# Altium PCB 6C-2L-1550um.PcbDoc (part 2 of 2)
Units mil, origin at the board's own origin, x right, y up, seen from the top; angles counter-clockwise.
Board outline 3937.01 x 2952.76 mil, 2 copper layers (Top Layer, Bottom Layer), stack 62.442 mil thick; 172 components, 97 nets, 523 pads, 239 vias.
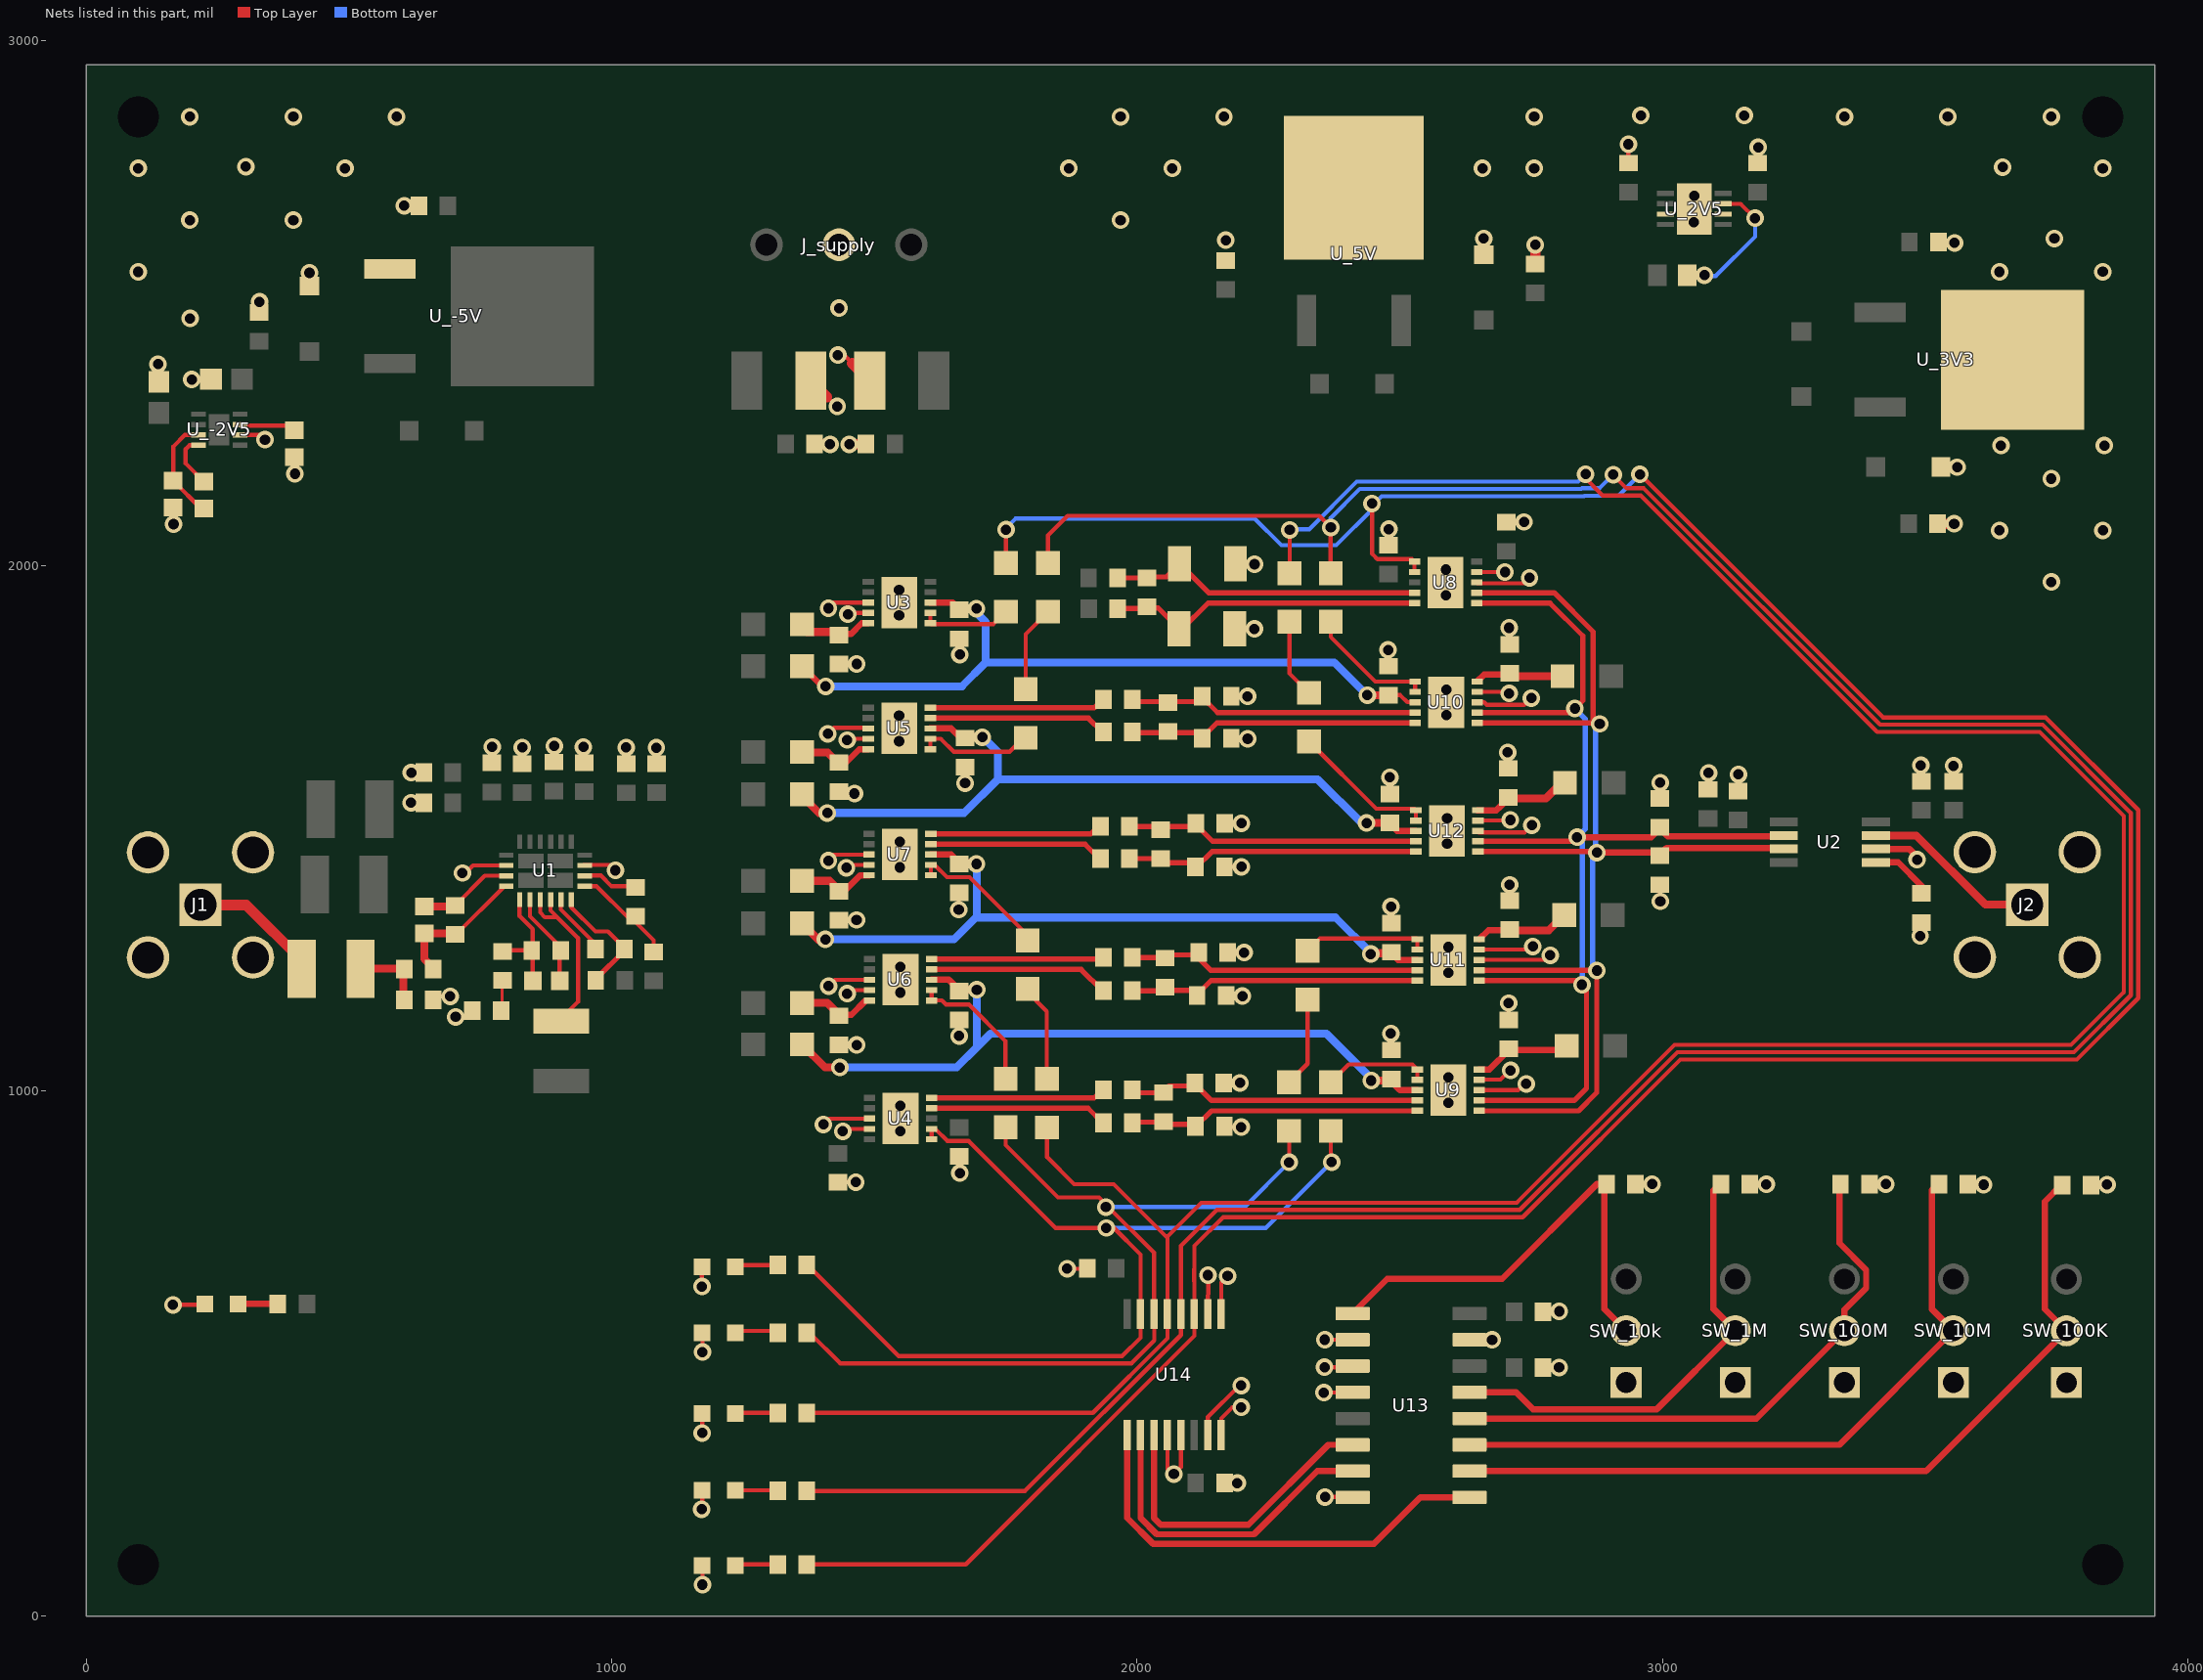
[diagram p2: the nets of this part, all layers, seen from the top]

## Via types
v1: diameter 33.46, hole 19.68, Top Layer to Bottom Layer, 215 vias
v2: diameter 37/37 (per signal layer), hole 19.7, Top Layer to Bottom Layer, 16 vias
v3: diameter 33.47, hole 19.69, Top Layer to Bottom Layer, 4 vias
v4: diameter 37, hole 19.7, Top Layer to Bottom Layer, 4 vias

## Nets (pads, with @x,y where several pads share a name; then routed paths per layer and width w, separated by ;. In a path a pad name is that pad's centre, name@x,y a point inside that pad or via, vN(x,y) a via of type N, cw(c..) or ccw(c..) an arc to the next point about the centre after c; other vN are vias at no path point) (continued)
Diff_pair3_N: R8.2 U4.9 | length 337.2
  Top Layer w9.84: U4.9@1608.96,966.96 1906.56,966.96 R8.2@1933.87,939.65 ; R8.2@1933.87,939.65 1933.87,939.15 R8.2@1933.87,939.65
Diff_pair3_P: R7.2 U4.10 | length 336.6
  Top Layer w9.84: U4.10@1608.96,986.64 1918.15,986.64 1933.86,1002.35 R7.2@1933.86,997.18
Diff_pair4_N: R10.2 U5.9 | length 338.5
  Top Layer w9.84: U5.9@1606.39,1709.48 1907.3,1709.48 R10.2@1933.87,1682.91
Diff_pair4_P: R9.2 U5.10 | length 343.3
  Top Layer w9.84: U5.10@1606.39,1729.17 1917.91,1729.17 1933.86,1745.12 R9.2@1927.33,1751.65
Diff_pair5_N: R11.2 U6.10 | length 326.5
  Top Layer w9.84: U6.10@1608.7,1250.8 1930.82,1250.8 R11.2@1933.9,1253.88
Diff_pair5_P: R12.2 U6.9 | length 342
  Top Layer w9.84: U6.9@1608.7,1231.11 1893.46,1231.11 R12.2@1933.9,1190.67
Diff_pair6_N: R14.2 U7.9 | length 332
  Top Layer w9.84: U7.9@1607.43,1469.45 1900.99,1469.45 R14.2@1928.2,1442.24
Diff_pair6_P: R13.2 U7.10 | length 327.8
  Top Layer w9.84: U7.10@1607.43,1489.14 1911.27,1489.14 1926.79,1504.66 R13.2@1928.21,1503.24
Diff_Pair9_N: Rmatch-.2 U2.3 U8.2 U9.1 U10.1 U11.2 U12.1 | length 2443
  Top Layer w9.84: U8.2@2646.2,1948.23 2794.1,1948.23 2868.14,1874.19 2868.14,1703.11 v1@2870.86,1700.39 ; U10.1@2647.16,1700.39 v1@2870.86,1700.39 ; U12.1@2647.91,1455.48 2872.84,1455.48 2874.88,1453.44 v1(2875.23,1453.44) ; U9.1@2651.45,962.11 2840.28,962.11 2875.06,996.89 2875.06,1227.48 2876.08,1228.49 2879.04,1228.49 2880.19,1229.64 2875.06,1229.64 U11.2@2651.45,1229.64 ; v1(2875.38,1229.08) v1@2875.38,1229.64 ; v1(2880.59,1698.57) 2877.22,1698.57 2874.31,1698.57 2873.89,1698.57 2872.68,1698.57 v1@2870.86,1700.39 ; Rmatch-.2@2991.09,1453.44 Rmatch-.2@2995.1,1449.43
  Top Layer w12: v1@2874.88,1453.44 Rmatch-.2@2991.09,1453.44 ; Rmatch-.2@2995.1,1449.43 3008.21,1462.53 3228.92,1462.53 U2.3@3230.89,1460.56
  Bottom Layer w9.84: v1(2875.23,1453.44) v1@2874.88,1453.44 ; v1(2875.38,1229.08) v1(2875.38,1229.08) 2867.36,1237.21 2867.36,1445.92 v1@2874.88,1453.44 ; v1(2880.59,1698.57) 2877.22,1698.57 2872.6,1698.57 2872.6,1455.72 v1@2874.88,1453.44
Diff_Pair9_P: Rmatch+.2 U2.2 U8.1 U9.2 U10.2 U11.1 U12.2 | length 2308.6
  Top Layer w9.84: U8.1@2646.2,1928.54 2785.95,1928.54 2848.46,1866.03 2848.46,1742.99 v1(2833.41,1727.95) ; U10.2@2647.16,1720.07 v1@2825.61,1720.07 ; U12.2@2647.91,1475.17 2829.81,1475.17 v1(2837.68,1483.04) ; U9.2@2651.45,981.79 2832.13,981.79 2855.38,1005.05 2855.38,1193.43 2838.85,1209.96 U11.1@2651.45,1209.96
  Top Layer w12: v1(2837.68,1483.04) 2847.04,1483.04 2978.53,1483.04 2994.96,1499.47 3010.05,1484.38 3229.11,1484.38 U2.2@3230.89,1486.15
  Bottom Layer w9.84: v1(2833.41,1727.95) 2853.03,1708.33 2853.03,1706.84 2852.91,1706.73 2852.91,1498.28 2844.96,1490.32 v1(2837.68,1483.04) 2847.67,1473.05 2847.67,1203.03 v1(2846.73,1202.08)
Diff_pair21_N: C6.2 C15.1 R6.1 U8.10 | length 600.3
  Top Layer w9.84: R6.1@1964.95,1918.11 2017.58,1918.11 2018.64,1919.17 2039.99,1919.17 C6.2@2079.67,1879.48 2086.12,1879.48 2135.18,1928.54 U8.10@2528.09,1928.54
Diff_pair21_P: C5.2 C15.2 R5.1 U8.9 | length 598.3
  Top Layer w9.84: R5.1@1964.65,1976.3 2016.71,1976.3 2018.64,1978.23 2055.86,1978.23 C5.2@2080.88,2003.25 2135.9,1948.23 2525.83,1948.23 2526.96,1949.35 U8.9@2528.09,1948.23
Diff_pair31_N: C8.2 C16.1 R8.1 U9.10 | length 555
  Top Layer w9.84: R8.1@1986.43,940.54 2037.78,940.54 C16.1@2041.07,937.26 ; C16.1@2050.31,939.67 2053.83,936.15 2105.69,936.15 2109.25,932.59 2112.03,932.59 2141.55,962.11 U9.10@2534.14,962.11
Diff_pair31_P: C7.2 C16.2 R7.1 U9.9 | length 552
  Top Layer w9.84: R7.1@1992.92,1002.35 1998.96,996.32 C16.2@2041.07,996.32 ; C16.2@2050.31,998.73 2060.86,1009.28 C7.2@2108.2,1009.28 ; C7.2@2108.09,1015.32 2141.62,981.79 2141.85,981.79 U9.9@2533.34,981.79
Diff_pair41_N: C10.2 C17.1 R10.1 U10.10 | length 553.9
  Top Layer w9.84: R10.1@1992.03,1681.8 2058.87,1681.8 2111.15,1681.8 2122.22,1670.74 2151.87,1700.39 U10.10@2529.05,1700.39
Diff_pair41_P: C9.2 C17.2 R9.1 U10.9 | length 552.7
  Top Layer w9.84: R9.1@1992.92,1745.12 1997.18,1740.86 2058.87,1740.86 2116.77,1740.86 C9.2@2121.99,1746.07 ; C9.2@2122.22,1751.11 2153.25,1720.08 U10.9@2529.05,1720.08
Diff_pair51_N: C12.2 C18.1 R12.1 U11.10 | length 561.3
  Top Layer w9.84: R12.1@1994.78,1189.53 1996.99,1189.53 1998.12,1190.67 2048.4,1190.67 2053.4,1195.67 2057.72,1191.34 2105.74,1191.34 C12.2@2114.07,1183.01 ; C12.2@2112.27,1181.2 C12.2@2114.07,1183.01 ; U11.10@2534.58,1209.96 2356.45,1209.96 2297.32,1209.96 2141.02,1209.96 C12.2@2114.07,1183.01
Diff_pair51_P: C11.2 C18.2 R11.1 U11.9 | length 573.3
  Top Layer w9.84: R11.1@1992.96,1253.88 2052.55,1253.88 2053.4,1254.72 2057.3,1258.62 2103.39,1258.62 2111.73,1266.96 2115.1,1270.33 2115.1,1263.59 2115.34,1263.36 2115.34,1254.24 2139.94,1229.64 2289.17,1229.64 2364.61,1229.64 U11.9@2533.34,1229.64
Diff_pair61_N: C14.2 C19.1 R14.1 U12.10 | length 558.7
  Top Layer w9.84: R14.1@1987.26,1442.24 C19.1@2043.43,1442.24 ; C19.1@2045.23,1440 2051.2,1434.03 2101.28,1434.03 2109.25,1426.06 2113.05,1426.06 2142.47,1455.48 U12.10@2529.8,1455.48
Diff_pair61_P: C13.2 C19.2 R13.1 U12.9 | length 558.9
  Top Layer w9.84: R13.1@1987.26,1503.24 2045.37,1503.24 2103.82,1503.24 2109.55,1508.98 2143.36,1475.17 U12.9@2529.8,1475.17
GND: C1_supU1.2 C1_supU2.1 C1_U3.1 C1_U4.1 C1_U5.1 C1_U6.1 C1_U7.1 C1_U8.1 C1_U9.1 C1_U10.1 C1_U11.1 C1_U12.1 C2_supU1.2 C2_supU2.1 C2_U3.1 C2_U4.1 C2_U5.1 C2_U6.1 C2_U7.1 C2_U8.1 C2_U9.1 C2_U10.1 C2_U11.1 C2_U12.1 C3_supU1.2 C4_supU1.2 C5.1 C6.1 C7.1 C8.1 C9.1 C10.1 C11.1 C11_supU1.2 C11_supU2.1 C12.1 C13.1 C14.1 C15_1.1 C15_2.1 C15_3.2 C15_4.2 C22_supU1.2 C22_supU2.1 C33_supU1.2 C44_supU1.2 C_A.1 C_enU13.2 C_enU14.2 C_REG.1 C_supU13.2 C_supU14.2 Csupin1.1 Csupin2.1 Csupin3.1 Csupin4.1 Csupin5.1 Csupout1.1 Csupout2.2 Csupout3.1 Csupout4.1 Csupout5.1 Csw0.1 Csw1.1 Csw2.1 Csw3.1 Csw4.1 D11.1 D22.2 D33.1 J1.2 J1.3 J1.4 J1.5 J2.2 J2.3 J2.4 J2.5 J_supply.2 LED_1M.1 LED_10K.1 LED_10M.1 LED_100K.1 LED_100M.1 LED_ON.1 R1.1 R2.2 R_hyst.2 Rmatch+.1 Rmatch-.1 SW_1M.1 SW_10k.1 SW_10M.1 SW_100K.1 SW_100M.1 U1.9 U1.18 U2.6 U3.3 U3.4 U3.11 U4.3 U4.4 U4.11 U5.3 U5.4 U5.11 U6.3 U6.4 U6.11 U7.3 U7.4 U7.11 U8.3 U8.4 U8.11 U9.3 U9.4 U9.11 U10.3 U10.4 U10.11 U11.3 U11.4 U11.11 U12.3 U12.4 U12.11 U13.2 U13.3 U13.4 U13.8 U13.15 U14.4 U14.5 U14.7 U14.8 U14.9 U14.10 U_2V5.3 U_2V5.6 U_2V5.9 U_3V3.2 U_5V.2 U_-2V5.6 U_-5V.1 | length 5279.7
  Top Layer w7.87: v1(136.32,2383.46) 136.32,2351.01 136.69,2350.65 Csupout5.1@137.71,2349.62 ; v1(164.56,592.86) 221.25,592.86 222.36,591.75 LED_ON.1@225.03,594.42 ; C_A.1@164.69,2110.56 164.69,2087.42 164.6,2087.32 165.67,2086.25 v1(165.67,2078.71) ; U_-2V5.6@291.92,2248.61 330.73,2248.61 v1(339.79,2239.55) ; Csupout2.2@328.31,2472.75 328.04,2473.01 329.1,2474.08 v1(329.1,2502) ; C_REG.1@395.37,2206.09 396.84,2204.62 v1(396.84,2174.68) ; D22.2@424.49,2531.64 v1(424.49,2557.13) ; v1(604.8,2684.77) 630.46,2684.77 Csupin2.1@630.64,2684.58 ; v1(617.61,1548.64) C11_supU1.2@640.16,1548.64 ; v1(618.23,1605.57) 639.99,1605.57 C1_supU1.2@640.19,1605.77 ; R1.1@659.5,1173.17 R1.1@659.7,1173.17 ; R1.1@662.07,1173.18 662.16,1173.08 R1.1@669.19,1180.1 ; v1(692.09,1180.06) R1.1@669.23,1180.06 ; v1(702.78,1140.9) 719.41,1140.9 720.49,1141.98 731.79,1153.28 731.99,1153.47 R2.2@732.35,1153.11 ; v1(715.68,1414.71) 721.38,1414.71 735.73,1429.07 U1.18@798.99,1429.07 ; C2_supU1.2@772.03,1626.18 772.88,1627.03 772.44,1627.46 v1(772.44,1654.81) ; C22_supU1.2@829.12,1624.8 828.79,1625.14 829.42,1625.77 v1(829.42,1653.76) ; C44_supU1.2@890.02,1627.91 889.61,1628.31 890.4,1629.09 890.59,1629.29 v1(890.59,1656.39) ; v1(945.95,1654.75) 945.95,1649.48 946.81,1648.62 946.81,1628.84 C4_supU1.2@948.03,1627.62 ; U1.9@946.72,1430.06 1004.4,1430.06 1004.4,1419.86 v1(1007,1419.86) ; v1(1027.44,1653.53) 1027.44,1631.92 1027.72,1631.65 1029.7,1629.67 1026.19,1626.16 C33_supU1.2@1027.86,1624.48 ; v1(1171.31,203.57) 1171.31,211.56 1171.52,211.77 1172.17,212.42 LED_1M.1@1172.17,239.91 ; v1(1171.52,627.61) 1171.52,659.35 1170.02,660.84 1173.22,664.03 LED_100K.1@1172.17,665.08 ; v1(1172.05,348.68) 1172.05,356.57 1172.19,356.71 1173.02,357.54 1172.17,358.4 LED_100M.1@1172.17,386.17 ; LED_10K.1@1172.17,96.69 1171.9,96.42 1172.59,95.72 v1(1172.59,60.01) ; LED_10M.1@1172.17,539.28 1172.59,538.86 v1(1172.59,502.67) ; v1@1394.42,936.2 v1(1402.95,936.2) 1414.03,947.27 U4.3@1490.85,947.27 ; v1@1405.61,1921.73 1408.65,1918.69 v1(1412.39,1918.69) 1412.39,1923.97 1406.75,1929.6 U3.3@1488.28,1929.6 ; 1409.83,2320.89 1423.16,2307.56 1427.98,2302.74 v1(1429.16,2302.74) ; v1(1411.43,1679.64) 1422.82,1691.03 1487.05,1691.03 U5.3@1488.28,1689.8 ; v1(1412.4,1438.27) 1412.4,1447.51 1414.66,1449.77 U7.3@1489.32,1449.77 ; v1(1412.53,1199.51) 1424.45,1211.43 U6.3@1490.59,1211.43 ; v1(1430.42,2400.53) 1442.41,2400.53 1444.25,2398.69 1450.21,2392.72 1457.77,2385.17 ; C1_U4.1@1430.8,824.1 1432.42,825.71 1433.08,826.37 v1(1464.52,826.37) ; C1_U7.1@1432.62,1323.1 1433.92,1321.8 1437.48,1325.36 v1(1465.9,1325.36) ; C1_U6.1@1432.77,1085.9 1433.94,1084.72 1436.54,1087.32 v1(1466.23,1087.32) ; C1_U3.1@1432.77,1812.53 1459.13,1812.53 1461.1,1810.57 1465.36,1810.57 1464.45,1809.65 1466.19,1811.4 v1(1466.19,1812.64) ; C1_U5.1@1434.18,1569.46 1437.63,1566 v1(1461.85,1566) ; v1(1439.44,922.91) 1444.13,927.59 U4.4@1490.85,927.59 ; v1(1446.47,1424.83) 1451.73,1430.08 U7.4@1489.32,1430.08 U7.4@1488.31,1431.09 ; v1(1447.85,1667.86) 1450.1,1670.11 U5.4@1488.28,1670.11 ; v1(1448.16,1185.12) 1454.78,1191.74 U6.4@1490.59,1191.74 ; v1(1449.32,1907.32) 1451.92,1909.92 U3.4@1488.28,1909.92 ; C15_1.1@1481.52,2230.79 C15_1.1@1481.85,2231.11 ; v1(1660.47,1344.91) 1660.47,1374.25 1660.54,1374.32 C2_U7.1@1661.31,1375.08 ; v1(1661.04,1104.7) 1661.04,1132.81 C2_U6.1@1661.12,1132.89 ; C2_U3.1@1661.12,1858.57 1661.91,1857.78 1662.51,1857.18 v1(1662.51,1830.48) ; C2_U4.1@1661.52,873.11 1661,872.59 1664.34,869.25 1662.43,867.34 v1(1662.43,843.61) ; C2_U5.1@1672.21,1614.54 1673.05,1613.69 1672.57,1613.21 v1(1672.57,1585.91) ; v1(1866.94,661.54) 1899.56,661.54 1900.4,662.38 1901.58,661.21 1902.48,660.31 C_supU14.2@1902.93,660.76 ; U14.4@2057.78,344.72 2057.94,344.56 2057.94,279.35 2066.64,270.65 v1(2069.93,270.65) 2083.37,284.1 U14.5@2083.37,344.72 ; U14.7@2134.55,344.72 2134.55,379.2 2194.43,439.07 v1(2198.22,439.07) ; U14.10@2134.55,575.22 2135.74,649.13 2135.75,649.87 v1@2134.94,650.68 ; C7.1@2158.58,1003.8 2158.58,1004.25 2158.66,1004.17 2170.2,1015.71 2170.58,1015.33 v1(2195.91,1015.33) ; C8.1@2159.74,921.07 2159.93,920.87 2171.48,932.42 2171.63,932.28 2173.17,933.81 2173.82,934.47 2177.33,930.96 v1(2198.1,930.96) ; U14.8@2160.14,344.72 2160.14,376.35 2181.38,397.6 v1(2198.22,397.6) ; U14.9@2160.14,575.22 2160.14,635.4 v1(2172.4,647.65) ; C_enU14.2@2168.44,253.37 v1(2190.75,253.37) ; C13.1@2168.61,1508.98 2168.94,1508.65 2193.56,1508.65 2194.34,1509.43 v1(2198.66,1509.43) ; C14.1@2168.89,1426.64 2193.73,1426.64 2193.84,1426.54 v1(2198.66,1426.54) ; C12.1@2171.32,1181.2 2171.32,1181.68 2173.07,1179.93 2173.68,1180.54 v1(2200.68,1180.54) ; C11.1@2174.39,1263.36 2176.95,1260.8 2179.43,1263.27 v1(2203.57,1263.27) ; C10.1@2181.27,1670.74 2181.61,1670.4 2181.88,1670.13 v1(2210.54,1670.13) ; C9.1@2181.27,1751.11 2184.76,1754.6 2189.37,1749.99 2190.47,1751.09 v1(2210.3,1751.09) ; C6.1@2185.97,1879.48 2186.37,1879.09 2186.59,1879.31 v1(2223.14,1879.31) ; C5.1@2187.12,2003.31 2188.75,2001.68 2189.51,2002.44 v1(2223.55,2002.44) ; v1(2355.25,425.69) 2409.83,425.69 U13.4@2410.36,426.22 ; v1(2357.04,473.86) 2408,473.86 U13.3@2410.36,476.22 ; v1(2357.4,526.35) 2410.23,526.35 U13.2@2410.36,526.22 ; v1(2357.89,227) 2409.58,227 2409.66,226.91 U13.8@2410.36,226.22 ; v1(2477.7,1839.44) 2477.7,1815.52 2477.58,1815.41 C2_U10.1@2482.57,1810.42 ; C2_U8.1@2478.86,2040.95 2480.38,2042.46 2480.03,2042.81 2479.18,2043.66 v1(2479.18,2069.02) ; v1(2481.03,1597) 2481.03,1567.7 C2_U12.1@2481.44,1567.3 ; v1(2483.08,1109.22) 2483.08,1081.09 2482.75,1080.75 C2_U9.1@2483.72,1079.78 ; v1(2483.5,1350.62) 2483.5,1321.79 C2_U11.1@2484.31,1320.98 ; U10.11@2588.1,1739.76 U10.11@2590.26,1741.92 ; U13.15@2632.8,526.22 2633.02,526.44 2633.26,526.19 v1(2675.82,526.19) ; U8.3@2646.2,1967.91 2648.13,1965.98 2736.82,1965.98 2747.04,1976.2 v1(2747.04,1976.56) ; U8.4@2646.2,1987.6 v1(2700.14,1987.6) ; U10.3@2647.16,1739.76 U10.3@2647.25,1739.76 2660.47,1739.76 2665.39,1734.84 2736.95,1734.84 2746.18,1744.06 2750.43,1744.06 v1(2750.43,1747.63) ; U10.4@2647.16,1759.45 U10.4@2647.25,1759.45 2708.18,1759.45 v1(2708.18,1756.35) v1@2708.27,1756.35 ; U12.3@2647.91,1494.85 2650.6,1492.16 2737.91,1492.16 v1(2751.3,1505.56) ; U12.4@2647.91,1514.54 U12.4@2648.77,1514.54 2709.21,1514.54 v1(2710.39,1515.72) ; U9.3@2651.45,1001.48 2725.17,1001.48 2736.99,1013.29 v1(2740.61,1013.29) ; U9.4@2651.45,1021.16 2651.64,1021.36 2691.59,1021.36 2709.24,1039.01 v1(2710.85,1039.01) ; U11.3@2651.45,1249.33 2651.52,1249.4 2779.78,1249.4 2786.5,1256.12 v1(2786.5,1258.27) ; U11.4@2651.45,1269.01 2742.43,1269.01 2748.46,1275.04 v1(2753.34,1275.04) ; C1_U8.1@2703.02,2084.13 2703.62,2084.73 2702.63,2085.72 2705.4,2082.95 v1(2736.7,2082.95) ; v1(2705.38,1644.54) 2705.38,1617.09 C1_U12.1@2706.6,1615.87 ; v1(2707.07,1167.14) 2707.07,1137.72 C1_U9.1@2707.71,1137.08 ; v1(2708.2,1881.42) 2708.2,1852.68 C1_U10.1@2709.06,1851.82 ; v1(2709.09,1392.36) 2709.09,1367.53 2708.9,1367.34 2707.83,1366.27 C1_U11.1@2709.67,1364.43 ; Csupout1.1@2758,2576.24 Csupout1.1@2758.24,2576.48 ; C_supU13.2@2774.66,579.2 2799.65,579.2 2800.74,580.29 v1(2803.63,580.29) ; C_enU13.2@2774.84,473.57 2775.18,473.57 2775.63,473.12 2776.05,473.55 v1(2803.38,473.55) ; v1(2935.15,2801.91) 2935.15,2766.74 Csupout4.1@2935.8,2766.09 ; Csw0.1@2950.35,822.39 2950.6,822.65 2950.64,822.69 v1(2980.41,822.69) ; Rmatch+.1@2994.21,1564.85 3000.39,1571.03 2994.26,1577.16 2994.63,1577.53 2995.76,1578.65 v1(2995.76,1586.84) ; Rmatch-.1@2995.1,1390.37 v1@2995.1,1372.11 ; v1(2995.95,1360.74) 2995.95,1370.58 2994.77,1371.77 v1@2995.1,1372.11 ; v1@2996.64,1359.69 2995.1,1361.22 v1@2995.1,1372.11 ; C11_supU2.1@3086.75,1575.79 3085.78,1576.76 3086.24,1577.22 3086.24,1595.92 3086.36,1595.8 3086.36,1596.66 3087.89,1598.19 v1(3087.89,1605.23) ; C1_supU2.1@3143.16,1574.18 3146.68,1577.7 C1_supU2.1@3154.02,1577.7 ; v1(3144.49,1602.57) 3144.49,1593.13 3143.08,1591.71 3143.67,1591.12 3142.13,1589.58 C1_supU2.1@3154.02,1577.7 ; C1_supU2.1@3156.47,1575.25 C1_supU2.1@3154.02,1577.7 ; Csw1.1@3168.25,822.39 3168.64,822.79 3169.55,821.89 v1(3197.76,821.89) ; Csupin4.1@3181.39,2766.09 3182.53,2767.23 v1(3182.53,2795.94) ; Csw2.1@3396.02,822.39 3397.26,823.63 3398.95,821.94 3399.53,822.53 v1(3425.21,822.53) ; R_hyst.2@3489.72,1318.64 3490.69,1317.67 v1(3490.69,1294.98) ; C2_supU2.1@3489.74,1591.24 3491.88,1593.38 v1(3491.88,1619.81) ; Csupin3.1@3527.36,2615.42 3528.61,2614.17 v1(3556.2,2614.17) ; Csw3.1@3583.62,822.39 3583.74,822.51 3609.01,822.51 3607.7,821.19 3607,821.19 3607.66,820.53 3608.49,821.36 v1(3611.35,821.36) ; Csw4.1@3818.21,820.68 3818.64,821.11 3819.23,821.7 v1(3846.39,821.7) ; R1.1@669.19,1180.1 R1.1@669.23,1180.06
  Top Layer w12: U2.6@3406.39,1460.56 3407.02,1459.93 3470.67,1459.93 3484.88,1445.72 v1(3484.88,1440.2)
  Top Layer w15: v1(1084.78,1653.29) 1084.78,1624.62 1082.99,1622.83 C3_supU1.2@1084.96,1624.8 ; C22_supU2.1@3549.02,1595.09 3552.34,1598.41 3554.13,1600.2 v1(3554.13,1618.85)
  Top Layer w20: C15_4.2@1378.9,2351.82 1409.83,2320.89 ; C15_3.2@1385.84,2230.97 1385.96,2230.85 v1(1415.46,2230.85) ; v1(1452.13,2230.85) 1481.46,2230.85 C15_1.1@1481.52,2230.79 ; 1457.77,2385.17 C15_2.1@1491.11,2351.82 ; v1(2758.05,2610.27) 2758.05,2576.66 Csupout1.1@2758.24,2576.48 ; Csupout3.1@3523.95,2079.3 3524.02,2079.23 3524.17,2079.38 v1(3555.39,2079.38) ; D33.1@3529.99,2187.98 3549.03,2187.98 3549.82,2187.19 v1(3561.19,2187.19)
  other v1: 2135.02,649.14 3740.16,1968.5 3641.73,2066.93 3838.58,2066.93 3740.16,2165.35 3644.38,2228.52 3841.23,2228.52 200.42,2354.15 197.13,2470.46 1432.69,2489.88 98.43,2559.06 3641.73,2559.06 3838.36,2559.18 2168.89,2619.08 2659.61,2622.46 3746.12,2622.42 196.85,2657.48 393.7,2657.48 1968.5,2657.48 98.43,2755.91 492.13,2755.91 1870.08,2755.91 2066.93,2755.91 2657.48,2755.91 2755.91,2755.91 3838.36,2756.03 3647.87,2758.33 303.24,2759.4 196.85,2854.33 393.7,2854.33 590.55,2854.33 1968.5,2854.33 2165.35,2854.33 2755.91,2854.33 3346.46,2854.33 3543.31,2854.33 3740.16,2854.33 2959.12,2856.63 3155.97,2856.63
  other v2: 1549.48,922.97 1549.48,971.63 2592.82,977.12 2592.82,1025.79 1549.21,1187.12 1549.21,1235.78 1547.95,1425.46 1547.95,1474.13 1546.91,1665.49 1546.91,1714.16 2588.62,1715.4 2588.62,1764.07 1546.91,1905.29 2587.57,1943.55 1546.91,1953.96 2587.57,1992.22
  other v3: 3060.03,2653.75 3060.33,2703.84
  other v4: 2592.82,1224.97 2592.82,1273.63 2590.14,1470.49 2590.14,1519.16
NetC1_1: C1.1 J1.1 | length 252.2
  Top Layer w20: J1.1@216.97,1353.89 303.94,1353.89 409.89,1247.94 C1.1@409.89,1232.54
NetC1_2: C1.2 R1.2 Rg1+.2 | length 148.7
  Top Layer w15: C1.2@512.21,1232.94 599.84,1232.94 603.01,1229.76 R1.2@603.01,1173.18
NetC1_U3_2: C1_U3.2 R_J1.2 U3.5 | length 147.2
  Top Layer w12: R_J1.2@1357.31,1887.84 R_J1.2@1371.6,1873.55 ; C1_U3.2@1429.38,1873.55 1433.48,1869.45 1455.15,1869.45 1475.93,1890.23 U3.5@1488.28,1890.23
  Top Layer w15: R_J1.2@1371.6,1873.55 C1_U3.2@1429.38,1873.55
NetC1_U5_2: C1_U5.2 R_J3.2 U5.5 | length 150.5
  Top Layer w12: C1_U5.2@1432.62,1624.98 1433.44,1624.16 1444.99,1624.16 1471.26,1650.43 U5.5@1488.28,1650.43
  Top Layer w15: R_J3.2@1356.97,1644.34 1410.62,1644.34 1429.97,1624.98 C1_U5.2@1432.62,1624.98
NetC1_U6_2: C1_U6.2 R_J5.2 U6.5 | length 149.2
  Top Layer w7.87: U6.5@1482.5,1171.34 1489.68,1171.34 1490.39,1172.06 U6.5@1490.59,1172.06
  Top Layer w12: C1_U6.2@1432.77,1144.95 1456.11,1144.95 U6.5@1482.5,1171.34
  Top Layer w15: R_J5.2@1361.89,1167.33 1410.39,1167.33 C1_U6.2@1432.77,1144.95
NetC1_U7_2: C1_U7.2 R_J9.2 U7.5 | length 146.4
  Top Layer w7.87: C1_U7.2@1432.62,1382.16 C1_U7.2@1444.47,1382.16
  Top Layer w12: C1_U7.2@1444.47,1382.16 1472.71,1410.4 U7.5@1489.32,1410.4
  Top Layer w15: R_J9.2@1361.89,1399.83 1414.95,1399.83 C1_U7.2@1432.62,1382.16
NetC1_U9_2: C1_U9.2 R_J11.1 U9.5 | length 184.8
  Top Layer w12: U9.5@2651.45,1040.85 2670.54,1040.85 2707.71,1078.03 2810.17,1078.03 R_J11.1@2817.69,1085.56
NetC1_U10_2: C1_U10.2 R_J12.1 U10.5 | length 169.7
  Top Layer w12: U10.5@2647.16,1779.13 2660.79,1792.76 C1_U10.2@2709.06,1792.76
  Top Layer w15: C1_U10.2@2709.06,1792.76 2712.63,1789.19 R_J12.1@2809.72,1789.19
NetC1_U11_2: C1_U11.2 R_J13.1 U11.5 | length 181.3
  Top Layer w12: U11.5@2651.45,1288.7 2668.8,1306.05 2709,1306.05 C1_U11.2@2709.67,1305.38
  Top Layer w15: C1_U11.2@2709.67,1305.38 2783.47,1305.38 R_J13.1@2813,1334.9
NetC1_U12_2: C1_U12.2 R_J14.1 U12.5 | length 193
  Top Layer w12: U12.5@2647.91,1534.22 2684,1534.22 2689.81,1540.02 C1_U12.2@2706.6,1556.82
  Top Layer w15: C1_U12.2@2706.6,1556.82 2778.37,1556.82 2807.9,1586.35 R_J14.1@2814.43,1586.35 R_J14.1@2819.35,1586.35
NetC_A_2: C_A.2 C_AFB.2 U_-2V5.3 | length 203.6
  Top Layer w7.87: C_A.2@164.69,2161.75 C_A.2@165.47,2160.97 ; U_-2V5.3@212.99,2248.61 187.38,2248.61 165.47,2226.7 C_A.2@165.47,2160.97 ; C_AFB.2@223.76,2108.18 218.26,2108.18 C_A.2@165.47,2160.97
NetC_AFB_1: C_AFB.1 U_-2V5.4 | length 104.1
  Top Layer w7.87: U_-2V5.4@212.99,2228.93 196,2228.93 188.73,2221.66 188.73,2194.39 C_AFB.1@223.76,2159.36
NetC_REG_2: C_REG.2 U_-2V5.7 | length 108
  Top Layer w7.87: U_-2V5.7@291.92,2268.3 294.09,2266.13 386.51,2266.13 C_REG.2@395.37,2257.27
NetCf+_1: Cf+.1 Rf-.2 Rg1-.2 U1.1 | length 225.2
  Top Layer w7.87: Rg1-.2@792.35,1267.62 848.93,1267.62 Rf-.2@849.37,1267.18 ; U1.1@824.15,1366.42 824.15,1332.99 849.47,1307.68 849.47,1267.08 Rf-.2@849.37,1267.18 ; Cf+.1@849.37,1209.13 Rf-.2@849.37,1267.18
NetCf+_2: Cf+.2 Rf-.1 U1.2 | length 183.7
  Top Layer w7.87: U1.2@844.14,1366.11 844.14,1332.49 904.56,1272.07 904.56,1267.21 900.55,1263.2 Cf+.2@900.55,1209.13
NetCf-_1: Cf-.1 Rf+.2 Rg1+.1 U1.20 | length 271.4
  Top Layer w7.87: Rf+.2@701.67,1295.73 795.63,1389.7 U1.20@798.99,1389.7
  Top Layer w15: Rg1+.1@662.07,1232.23 643.3,1251 Cf-.1@643.3,1299.67 697.73,1299.67 Rf+.2@701.67,1295.73
NetCf-_2: Cf-.2 Rf+.1 U1.19 | length 179.9
  Top Layer w7.87: Rf+.1@701.67,1354.79 703.64,1354.79 758.23,1409.38 U1.19@798.99,1409.38
  Top Layer w15: Cf-.2@643.3,1350.85 697.73,1350.85 Rf+.1@701.67,1354.79
NetCsw0_2: Csw0.2 SW_10k.2 U13.1 | length 879.7
  Top Layer w12: U13.1@2410.36,576.22 2476.15,642.01 2694.67,642.01 2875.05,822.39 2891.29,822.39 2889.69,820.8 2889.69,659.14 2889.6,659.04 2889.6,584.89 SW_10k.2@2931.03,543.46
NetCsw1_2: Csw1.2 SW_1M.2 U13.13 | length 882.1
  Top Layer w12: U13.13@2632.8,426.22 2721.44,426.22 2753.53,394.12 2989.38,394.12 SW_1M.2@3138.72,543.46 3097.29,584.89 3097.29,810.49 Csw1.2@3109.19,822.39
NetCsw2_2: Csw2.2 SW_100M.2 U13.12 | length 1100.1
  Top Layer w12: U13.12@2632.8,376.22 3179.16,376.22 SW_100M.2@3346.41,543.46 3346.41,583.29 3387.84,624.72 3387.84,659.04 3336.97,709.92 Csw2.2@3336.97,822.39
NetCsw3_2: Csw3.2 SW_10M.2 U13.11 | length 1327.6
  Top Layer w12: U13.11@2632.8,326.22 3336.85,326.22 SW_10M.2@3554.1,543.46 3512.66,584.89 3512.66,624.72 3512.66,659.04 3512.66,810.49 Csw3.2@3524.57,822.39
  Bottom Layer w12: SW_10M.2@3554.1,528.21 SW_10M.2@3554.1,543.46
NetCsw4_2: Csw4.2 SW_100K.2 U13.10 | length 1554.7
  Top Layer w12: U13.10@2632.8,276.22 3502.26,276.22 SW_100K.2@3769.21,543.16 3727.77,584.59 3727.77,624.42 3727.77,658.75 3727.77,789.3 Csw4.2@3759.16,820.68
NetJ2_1: J2.1 U2.7 | length 342.8
  Top Layer w15: U2.7@3406.39,1486.15 3483.24,1486.15 3615.01,1354.38 J2.1@3694.6,1354.38
NetLED_1M_2: LED_1M.2 R_LED1.1 | length 79.2
  Top Layer w7.87: LED_1M.2@1235.16,239.91 1312.32,239.91 R_LED1.1@1313.78,238.45
NetLED_10k_2: LED_10K.2 R_LED0.1 | length 79.4
  Top Layer w7.87: LED_10K.2@1235.16,96.69 1237.08,98.6 R_LED0.1@1313.78,98.6
NetLED_10M_2: LED_10M.2 R_LED3.1 | length 79
  Top Layer w7.87: LED_10M.2@1235.16,544.17 1236.11,543.21 R_LED3.1@1313.78,543.21
NetLED_100K_2: LED_100K.2 R_LED4.1 | length 80
  Top Layer w7.87: LED_100K.2@1235.16,665.08 1238.4,668.32 R_LED4.1@1313.78,668.32
NetLED_100M_2: LED_100M.2 R_LED2.1 | length 79
  Top Layer w7.87: LED_100M.2@1235.16,386.17 1236.11,387.12 R_LED2.1@1313.78,387.12
NetLED_ON_2: LED_ON.2 R_LED_ON.1 | length 73.8
  Top Layer w12: LED_ON.2@288.53,594.41 R_LED_ON.1@362.37,594.41
NetR2_1: R2.1 Rg1-.1 | length 55.8
  Top Layer w5.91: R2.1@791.4,1153.11 791.4,1207.62 Rg1-.1@792.35,1208.56
NetR_hyst_1: R_hyst.1 U2.5 | length 119
  Top Layer w7.87: U2.5@3405.45,1434.97 U2.5@3406.39,1434.97
  Top Layer w12: U2.5@3406.39,1434.97 3448.78,1434.97 3493.12,1390.64 R_hyst.1@3493.12,1377.69
NetR_J0_2: R_J0.2 U1.3 U1.4 | length 333.3
  Top Layer w7.87: U1.3@863.52,1366.42 863.52,1339.54 872.41,1330.66 895.96,1330.66 ; U1.4@883.21,1366.42 883.21,1343.4 895.47,1331.15 895.96,1330.66 ; R_J0.2@899.21,1132.93 935.69,1169.41 935.69,1290.92 895.96,1330.66
NetR_J15_1: R_J15.1 R_LED0.2 U8.6 U8.7 U14.11 | length 6220.9
  Top Layer w7.87: R_LED0.2@1372.83,98.6 1673.83,98.6 2108.96,533.74 U14.11@2108.96,575.22 2108.96,637.61 2108.44,638.13 2108.44,660.15 2108.96,660.67 2108.96,704.79 2163.75,759.58 2734.05,759.58 3034.32,1059.84 3789.13,1059.84 3905.66,1176.38 3905.66,1534.73 3729.63,1710.77 3420.14,1710.77 v1(2957.3,2173.61) ; R_J15.1@1750.14,2004.73 1750.14,2068.13 v1(1750.43,2068.42) ; v1(2447.15,2118) 2447.15,2022.4 2448.17,2021.37 2449.49,2020.06 2457.53,2012.01 2523.36,2012.01 U8.6@2528.09,2007.28 U8.7@2528.09,1987.6
  Bottom Layer w7.87: v1(1750.43,2068.42) 1750.43,2071.46 1768.31,2089.34 2223.96,2089.34 2274.69,2038.62 2378.93,2038.62 2448.17,2107.85 2447.15,2108.88 v1(2447.15,2118) ; v1@2447.15,2115.85 2448.17,2114.83 2465.35,2132.01 2851.08,2132.01 2851.85,2132.78 2916.47,2132.78 v1(2957.3,2173.61)
NetR_J15_2: R_J15.2 U3.6 U3.7 | length 173.9
  Top Layer w7.87: U3.7@1606.39,1909.92 U3.6@1606.39,1890.23 1608.02,1888.6 1726.53,1888.6 R_J15.2@1750.14,1912.21
NetR_J16_1: R_J16.1 R_J26.1 R_LED1.2 U14.12 | length 5901.2
  Top Layer w7.87: R_LED1.2@1372.83,238.45 1786.63,238.45 2083.37,535.19 U14.12@2083.37,575.22 2083.37,704.79 2151.93,773.36 2728.34,773.36 3028.61,1073.62 3783.42,1073.62 3891.88,1182.09 3891.88,1529.02 3723.92,1696.99 3414.43,1696.99 2964.38,2147.03 2932.09,2147.03 v1(2906.27,2172.86) ; R_J16.1@1830.41,2004.54 1830.41,2057.21 1867.56,2094.36 2346.77,2094.36 2368.32,2072.81 2368.32,1985.81 R_J26.1@2368.63,1985.51 ; v1@2368.32,2072.47 v1(2368.66,2072.47)
  Bottom Layer w7.87: v1(2368.66,2072.47) 2368.32,2072.81 2368.32,2090.23 2423.94,2145.85 2845.43,2145.85 2846.9,2147.32 2880.72,2147.32 v1(2906.27,2172.86)
NetR_J16_2: R_J16.2 R_J17.1 | length 168.9
  Top Layer w7.87: R_J17.1@1787.7,1760.83 1787.7,1869.31 R_J16.2@1830.41,1912.02
NetR_J17_2: R_J17.2 U5.6 U5.7 | length 222.3
  Top Layer w7.87: U5.6@1606.39,1650.43 U5.7@1606.39,1670.11 1626.33,1670.11 1650.99,1645.46 1757.46,1645.46 1783.94,1671.93 R_J17.2@1787.87,1671.93
NetR_J18_1: R_J18.1 R_J19.2 | length 187.9
  Top Layer w7.87: R_J19.2@1786.06,1193.33 1827.98,1151.41 1827.98,1023.31 R_J18.1@1828.37,1022.92
NetR_J18_2: R_J18.2 R_J24.1 R_LED2.2 U14.13 | length 5630.7
  Top Layer w7.87: R_LED2.2@1372.83,387.12 1915.82,387.12 2057.78,529.09 U14.13@2057.78,575.22 2057.78,719.83 1955.4,822.21 1880.31,822.21 1828.37,874.15 R_J18.2@1828.37,930.4 ; 2057.78,723.02 2121.89,787.14 2722.63,787.14 3022.9,1087.4 3777.71,1087.4 3878.1,1187.8 3878.1,1523.32 3718.21,1683.21 3408.72,1683.21 2958.68,2133.25 2886.43,2133.25 2848.95,2170.73 2850.24,2172.02 2853.98,2172.02 2853.98,2173.14 v1(2853.98,2173.89) ; R_J24.1@2289.88,1985.51 2293.91,1989.55 2290.59,1992.88 v1(2290.59,2067.78)
  Bottom Layer w7.87: v1(2290.59,2067.78) 2290.59,2069.11 2327.72,2069.11 2418.24,2159.63 2839.72,2159.63 v1(2853.98,2173.89)
NetR_J19_1: R_J19.1 U7.6 U7.7 | length 268.9
  Top Layer w7.87: U7.6@1607.43,1410.4 U7.7@1607.43,1430.08 1614.48,1430.08 1637.98,1406.58 1681,1406.58 1791.58,1295.99 R_J19.1@1791.58,1286.44
NetR_J20_1: R_J20.1 U6.6 U6.7 | length 269
  Top Layer w7.87: U6.7@1608.7,1191.74 U6.6@1608.7,1172.06 1628.38,1172.06 1636.05,1164.39 1680.01,1164.39 1749.18,1095.22 R_J20.1@1749.18,1018.16
NetR_J20_2: R_J20.2 R_J22.2 R_LED3.2 U14.14 | length 1714
  Top Layer w7.87: R_LED3.2@1376.77,539.28 1434.7,481.34 1989.39,481.34 2032.91,524.86 2032.91,574.51 U14.14@2032.19,575.22 2032.19,692.11 1945.44,778.86 v1(1940.59,778.86) 1940.59,784.41 1927.63,797.36 1849.25,797.36 1749.62,896.99 R_J20.2@1749.62,930.57 ; R_J22.2@2288.88,923.61 2289.45,923.04 v1(2289.45,863.86)
  Bottom Layer w7.87: v1(1940.59,778.86) 2204.46,778.86 v1(2289.45,863.86)
NetR_J21_1: R_J21.1 U9.6 U9.7 | length 202.4
  Top Layer w7.87: R_J21.1@2368.63,1016.13 2402.68,1050.18 2524.01,1050.18 U9.6@2533.34,1040.85 U9.7@2533.34,1021.16
NetR_J21_2: R_J21.2 R_LED4.2 U4.6 U4.7 U14.15 | length 1935.4
  Top Layer w7.87: R_LED4.2@1372.83,668.32 1546.03,495.12 1971.5,495.12 2006.6,530.22 U14.15@2006.6,575.22 2006.6,688.43 1956.01,739.03 v1(1941.43,739.03) 1844.96,739.03 1679.38,904.61 1638.75,904.61 1615.77,927.59 U4.7@1608.96,927.59 U4.6@1608.96,907.9 ; R_J21.2@2368.63,923.61 2368.63,866.42 v1(2370.44,864.6)
  Bottom Layer w7.87: v1(1941.43,739.03) 2244.86,739.03 v1(2370.44,864.6)
NetR_J22_1: R_J22.1 R_J23.2 | length 172.6
  Top Layer w7.87: R_J22.1@2288.88,1016.13 2324.59,1051.84 R_J23.2@2324.59,1173.94
NetR_J23_1: R_J23.1 U11.6 U11.7 | length 238.9
  Top Layer w7.87: R_J23.1@2324.59,1266.46 2348.32,1290.19 2531.84,1290.19 U11.6@2533.34,1288.7 U11.7@2533.34,1269.01
NetR_J24_2: R_J24.2 R_J25.1 | length 150.9
  Top Layer w7.87: R_J24.2@2289.88,1892.99 2289.88,1795.02 R_J25.1@2327.31,1757.59
NetR_J25_2: R_J25.2 U12.6 U12.7 | length 277.2
  Top Layer w7.87: R_J25.2@2327.31,1665.07 2455.29,1537.1 2527.79,1537.1 U12.6@2530.66,1534.22 U12.7@2530.66,1514.54
NetR_J26_2: R_J26.2 U10.6 U10.7 | length 244.3
  Top Layer w7.87: R_J26.2@2368.63,1892.99 2368.63,1864.07 2453.57,1779.13 U10.6@2529.14,1779.13 U10.7@2529.14,1759.45
NetRf2+_1: Rf2+.1 U1.8 | length 96.1
  Top Layer w7.87: U1.8@948.59,1409.38 949.17,1409.96 979.32,1409.96 999.87,1389.4 Rf2+.1@1035.99,1389.4
NetRf2+_2: Rf2+.2 Rg2+.1 U1.7 | length 199.6
  Top Layer w7.87: U1.7@948.59,1389.7 970.84,1389.7 1030.19,1330.35 1038.61,1330.35 Rf2+.2@1045.17,1330.35 ; Rf2+.2@1038.61,1327.73 1079.74,1286.59 Rg2+.1@1079.74,1266.34
NetRf2-_1: Rf2-.1 U1.5 | length 123
  Top Layer w7.87: U1.5@902.89,1366.42 902.89,1345.31 962.71,1285.49 962.71,1274.4 Rf2-.1@967.07,1270.04
NetRf2-_2: Rf2-.2 Rg2-.1 U1.6 | length 237.2
  Top Layer w7.87: U1.6@922.58,1366.42 922.58,1349.59 968.69,1303.48 992.69,1303.48 1026.13,1270.04 Rf2-.2@1026.13,1269.17
  Top Layer w10: Rg2-.1@967.42,1210.46 Rf2-.2@1026.13,1269.17
NetRPG_1: RPG.1 U_2V5.7 | length 275.3
  Top Layer w7.87: RPG.1@3047.47,2552.49 3047.92,2552.94 RPG.1@3049.42,2551.45 ; RPG.1@3049.44,2551.43 3050.81,2552.8 v1(3079.9,2552.8) ; U_2V5.7@3115.63,2688.55 3148.96,2688.55 v1(3176.33,2661.18)
  Bottom Layer w7.87: v1@3073.17,2551.02 3101.46,2551.02 3176.33,2625.89 v1(3176.33,2661.18)
NetU13_6: U13.6 U14.3 | length 604.7
  Top Layer w12: U14.3@2032.19,344.72 2032.19,186.61 2044.93,173.88 2211.64,173.88 2363.98,326.22 U13.6@2410.36,326.22
NetU13_7: U13.7 U14.2 | length 624.2
  Top Layer w12: U14.2@2006.6,344.72 2006.63,186.85 2037.51,155.97 2222.63,155.97 2342.87,276.22 U13.7@2410.36,276.22
NetU13_9: U13.9 U14.1 | length 866.2
  Top Layer w12: U14.1@1981.01,344.72 1980.97,344.68 1980.97,187.19 2030.1,138.06 2450.97,138.06 2539.12,226.22 U13.9@2632.8,226.22
Vss_U7: C2_U7.2 C2_U11.2 R_J10.2 U7.8 U11.8 | length 1424.2
  Top Layer w12: U7.8@1607.43,1449.77 1645.68,1449.77 C2_U7.2@1661.31,1434.14 ; C2_U11.2@2484.31,1261.92 2496.91,1249.33 U11.8@2533.34,1249.33
  Top Layer w15: R_J10.2@1361.89,1318.95 v1@1395.08,1285.76 ; C2_U7.2@1661.31,1434.14 1687.97,1434.14 1688.65,1434.82 1691.55,1431.92 v1(1694.34,1431.92) ; v1(2444.94,1260.47) 2452.47,1260.47 2452.82,1260.82 2454.12,1262.12 2484.12,1262.12 C2_U11.2@2484.31,1261.92
  Bottom Layer w15: v1(1406.48,1288.31) 1651.62,1288.31 1693.33,1330.02 2377.53,1330.02 2444.94,1262.61 v1(2444.94,1260.47) ; v1(1694.34,1431.92) 1695.19,1431.07 1695.19,1330.02
Vss_U9: C2_U6.2 C2_U9.2 R_J6.2 U6.8 U9.8 | length 1472
  Top Layer w12: U6.8@1608.7,1211.43 1641.64,1211.43 C2_U6.2@1661.12,1191.95 ; C2_U9.2@2482.28,1019.29 2500.1,1001.48 U9.8@2533.34,1001.48
  Top Layer w15: R_J6.2@1361.89,1088.58 1405.92,1044.55 v1(1433.98,1044.55) ; C2_U6.2@1661.12,1191.95 1663.42,1194.24 1664.65,1193.01 1665.16,1192.5 v1(1694.83,1192.5) ; v1(2445.83,1019.55) 2455.21,1019.55 2455.81,1020.15 2454.95,1019.29 C2_U9.2@2482.28,1019.29
  Bottom Layer w15: v1(1433.98,1044.55) 1656.39,1044.55 1694.98,1083.14 ; v1(1694.83,1192.5) 1694.83,1190.79 1693.34,1189.3 1694.98,1187.66 1694.98,1083.14 ; v1(2445.83,1019.55) 2445.83,1023.36 2360.06,1109.13 1720.97,1109.13 1694.98,1083.14
Vss_U10: C2_U3.2 C2_U10.2 R_J2.2 U3.8 U10.8 | length 1453.7
  Top Layer w7.87: C2_U10.2@2478.86,1753.34 2500.8,1753.34 2514.37,1739.76 U10.8@2529.14,1739.76
  Top Layer w12: R_J2.2@1361.89,1808.46 1400.24,1770.12 v1(1407.02,1770.12) ; U3.8@1606.39,1929.6 1649.14,1929.6 C2_U3.2@1661.12,1917.62
  Top Layer w15: C2_U3.2@1661.12,1917.62 1690.74,1917.62 1690.29,1917.17 1687.13,1917.17 1688.07,1918.11 v1(1694.12,1918.11) ; v1(2438.11,1753.09) 2478.62,1753.09 C2_U10.2@2478.86,1753.34
  Bottom Layer w15: v1(1407.02,1770.12) 1666.6,1770.12 1711.77,1815.29 ; v1(1694.12,1918.11) 1688.07,1918.11 1687.13,1917.17 1711.77,1892.52 1711.77,1815.29 ; v1(2438.11,1753.09) 2375.48,1815.72 1712.2,1815.72 1711.77,1815.29
Vss_U12: C2_U5.2 C2_U12.2 R_J4.2 U5.8 U12.8 | length 1470.4
  Top Layer w12: U5.8@1606.39,1689.8 1645.89,1689.8 1664.07,1671.62 C2_U5.2@1672.21,1671.62 ; C2_U12.2@2481.38,1508.24 2494.77,1494.85 U12.8@2530.66,1494.85
  Top Layer w15: R_J4.2@1357.34,1565.8 1394,1529.14 v1(1410.25,1529.14) ; C2_U5.2@1672.21,1673.59 1701.15,1673.59 1702.95,1675.39 1704.39,1675.39 1705.49,1674.29 v1(1705.49,1673.11) ; v1(2436.93,1509.96) 2472.69,1509.96 2479.27,1503.38 2479.27,1508.04 C2_U12.2@2481.44,1510.21
  Bottom Layer w15: v1(1410.25,1529.14) 1670.99,1529.14 1735.03,1593.19 ; v1(1705.49,1673.11) 1705.49,1674.48 1704.39,1675.58 1735.03,1644.93 1735.03,1593.19 ; v1(2436.93,1509.96) 2427.05,1509.96 2343.82,1593.19 1735.03,1593.19
pads on no net: U_2V5.4

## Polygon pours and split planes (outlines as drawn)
+5V on Top Layer "+5V Layer" (solid, remove dead copper, pour order 64): 3195.78,2605.23 3166.94,2605.23 3160.75,2611.42 3160.75,2640.27 3147.16,2653.86 3103.88,2653.86 3103.88,2513.33 3006.54,2415.99 2881.97,2415.99 2785.79,2512.17 2729.59,2512.17 2677.86,2460.43 2481.32,2460.43 2477.39,2456.5 2477.39,2317.44 2486.59,2308.24 3095.64,2308.24 3241.03,2453.63 3446.2,2453.63 3446.2,2554.9 3465.81,2574.5 3465.81,2633.42 3374.37,2724.86 3108.62,2724.86 3100.12,2716.36 3100.12,2702.86 3155.34,2702.86 3162.14,2696.05 3186.65,2696.05 3214.91,2667.79 3214.91,2624.36
+2V5 on Top Layer "+2V5 Top Layer" (solid, remove dead copper, pour order 77): 3021.14,2714.16 3011.85,2723.45 2858.37,2723.45 2797.58,2662.67 2797.58,2539.99 2878.23,2459.35 2979.23,2459.35 2997.03,2477.15 2997.03,2621.08 2973.1,2645.02 2973.1,2674.06 2982.6,2683.56 2997.12,2683.56 3021.14,2683.56
-5V on Top Layer "-5V Layer" (solid, remove dead copper, pour order 36): 491.77,2224.67 620.94,2224.67 623.46,2227.19 623.46,2283.18 588.48,2318.15 588.48,2411.98 299.26,2411.98 277.15,2389.88 277.15,2339.91 232.77,2295.53 232.77,2228.63 238.36,2223.05 304.95,2223.05 305.91,2224.01 305.91,2233.93 272.92,2233.93 271.84,2235.01 271.84,2279.04 276.04,2283.24 433.2,2283.24
-2V5 on Top Layer "-2V5 Top Layer" (solid, pour order 76): 67.25,1838.9 31.18,1838.9 0,1870.08 0,2352.46 24.49,2352.46 76.95,2300 209.06,2300 214.55,2294.51 214.55,2262.37 173.91,2262.37 139.53,2228.04 134.49,2223.01 134.49,1906.15
GND on Top Layer "Top Ground 1" (solid, remove dead copper, pour order 56): 627.71,2654.48 590.55,2617.32 590.55,2533.9 402.7,2533.9 346.24,2477.45 345.91,2477.12 290.2,2477.12 258.32,2445.23 258.32,2344.64 247.16,2333.49 247.16,2333.44 85.08,2333.44 10.03,2408.49 10.03,2942.72 627.71,2942.72
+15V on Top Layer "+15V Layer" (solid, remove dead copper, pour order 53): 2344.89,2292.26 2344.89,2456.73 2341,2460.63 2264.92,2460.63 2203.01,2522.54 1808.16,2522.54 1771.65,2559.06 1771.65,2942.72 1529.49,2942.72 1529.49,2553.31 1534.93,2547.87 1599.26,2547.87 1599.26,2267.79 1595.35,2263.88 1560.69,2263.88 1540.37,2243.55 1540.37,2218.38 1546.86,2211.89 2264.52,2211.89
GND on Top Layer "Top Ground 0" (solid, remove dead copper, pour order 35): 1377.95,2204.96 1476.43,2204.95 1476.5,2263.78 1476.5,2952.64 1476.38,2952.76 1377.95,2952.76
-15V on Top Layer "-15V Layer" (solid, remove dead copper, pour order 58): 730.65,2281.08 730.65,2224.62 746.36,2208.92 1324.21,2208.92 1324.21,2252.47 1274.52,2252.47 1256.98,2270.01 1256.98,2547.76 1326.24,2547.76 1333.85,2555.37 1333.85,2942.72 688.98,2942.72 688.98,2322.76
3V3 on Top Layer "3V3 Layer" (solid, remove dead copper, pour order 42): 3462.92,2049.38 3305.62,2049.38 3237.3,2117.69 3237.31,2322.87 3415.14,2322.87 3415.14,2153.13 3462.92,2105.35
GND on Top Layer "Top Ground 2" (solid, remove dead copper, pour order 71): 3093.73,2731.76 3121.12,2759.15 3241.96,2759.15 3444.88,2759.15 3529.74,2674.29 3529.74,2044.43 3530.05,2044.12 3647.6,1926.57 3926.97,1926.57 3926.97,2942.72 1838.29,2942.72 1838.29,2629.58 1888.9,2578.97 2776.7,2578.97 2776.7,2678.28 2857.58,2759.15 2995.74,2759.15 3027.54,2727.35 3027.54,2677.64 3027.06,2677.17 2991.28,2677.17 2986.08,2671.97 2986.08,2665.28 2990.54,2660.83 3026.7,2660.83 3027.44,2660.09 3027.54,2660.09 3027.54,2628.25 3027.9,2627.88 3093.3,2627.88 3093.73,2628.31 3093.73,2660.09 3095.97,2662.34 3131.56,2662.34 3134.23,2665.01 3134.23,2672.89 3130.71,2676.41 3094.57,2676.41 3093.73,2677.25
GND on Bottom Layer "Botton Ground Layer" (solid, remove dead copper, pour order 75): 5.1,2943.71 5.1,10.11 3924.5,10.11 3924.5,2943.71
-2V5 on Bottom Layer "Botton Ground_-2V5" (solid, pour order 70): 926.01,1386.79 821.54,1386.79 821.54,1451.67 925.96,1451.67 926.01,1451.71

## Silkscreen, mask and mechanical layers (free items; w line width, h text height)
Top Overlay:
  lines w10: 718.02,145.25 666.58,196.69 770.78,196.69 719.34,145.25 ; 719.33,197.34 719.33,636.09
  text "OUT" at 3603.68,1101.98 h65.75
  text "IN" at 177.57,1099.22 h65.75
  text "Filter Priority :" at 503.12,769.21 h47.24
  text "ON" at 191.3,668.41 h65.75
  text "LOW / PRIORITY" at 643.92,649.49 h19.68
  text "Workshop   / Sistema Fotonico di trasmissione dati / Gruppo 2 - 2020 / - Bracchetti M.  / - Costa D.  / - Moles A." at 31.05,90.16 h35.43
  text "HIGHT / PRIORITY" at 650.05,71.62 h19.68
  text "100 Kbps /  / 10  Mbps /  / 100 Mbps /  /  1   Mbps /  / 10  kbps" at 807.75,39.59 h39.37
Mechanical 1:
  lines w7.87: 0,0 0,2952.76 ; 0,0 0,0 ; 0,0 3051.18,0 3937.01,0 3937.01,2952.76 0,2952.76 ; 0,2952.76 156.98,2952.76 0,2952.76
  text ".Pcb_File_Name_No_Path" at 95.87,-78.61 h60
